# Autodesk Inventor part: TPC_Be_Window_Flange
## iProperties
Shininess: 64.0
Length Units: 11269
Angle Units: 11279
Time Units: 11290
Mass Units: 11283
Length Display Precision: 3
Angle Display Precision: 2
Compacted: True
Part Number: TPC_Be_Window_Flange
Document SubType Name: Modeling
Created: 2004-07
Designer: John Blackburn
Manufacturer: Standard
Standards Organization: Custom
Project: Mucap
Material: Stainless Steel, Austenitic
Description: Mucap, Beryllium Window Flange
Density: 0.0
Volumn: 0.0
Area: 0.0
PropertySet Name: Model Information
Control State: 0
Master: False
Checked Out: False
Author: John Blackburn
Title: Mucap, Beryllium Window Flange
Subject: mucap
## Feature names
1. Extrusion1
2. Hole1
3. Circular Pattern1
4. Chamfer1
5. Extrusion2
